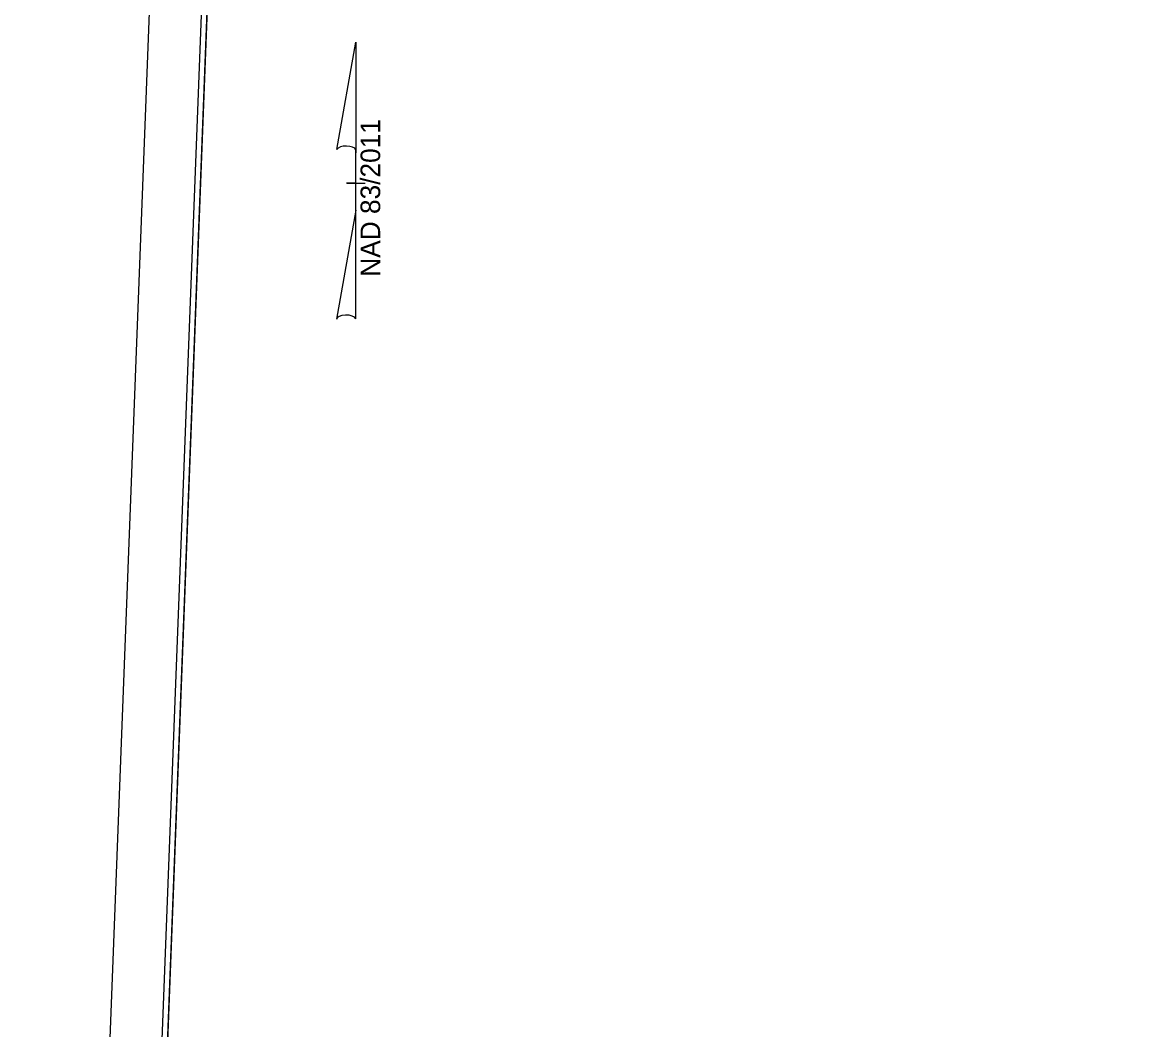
# Model space of a CAD drawing. Extents: x 2097096 to 2098260, y 686401 to 688363.
# Drawn here: x 2097096 to 2097581, y 687501.6 to 687937.5 of the extents above; entities that cross this region are included whole.
import ezdxf

# ---------------------------------------------------------------- set-up
doc = ezdxf.new("R2010")
doc.units = 0
for name, color, linetype in [('Prop North Arrow NAD83 for Plan Sheets CELL', 7, 'Continuous'), ('Sheet Layout Plan Border', 7, 'Continuous'), ('Sheet Plot Border Inside CELL', 7, 'Continuous'), ('Sheet Plot Border Outside CELL', 7, 'Continuous'), ('Sheet Profile CELL', 7, 'Continuous')]:
    doc.layers.add(name, color=color, linetype=linetype)

msp = doc.modelspace()

# ---------------------------------------------------------------- linework, layer by layer
at = {"layer": 'Prop North Arrow NAD83 for Plan Sheets CELL'}
for p, q in [((2097231.99, 687882.56), (2097240.19, 687928.91)), ((2097240.24, 687928.91), (2097240.19, 687928.91)), ((2097240.24, 687928.91), (2097240.19, 687928.91)), ((2097240.24, 687928.91), (2097240.24, 687881.11)), ((2097240.24, 687856.31), (2097240.24, 687882.51)), ((2097240.24, 687881.11), (2097240.24, 687882.46)), ((2097236.24, 687867.91), (2097236.19, 687867.91)), ((2097239.79, 687867.91), (2097236.24, 687867.91)), ((2097236.29, 687867.91), (2097244.29, 687867.91)), ((2097240.24, 687856.31), (2097231.89, 687809.06)), ((2097240.29, 687809.26), (2097240.24, 687856.31))]:
    msp.add_line(p, q, dxfattribs=at)
for centre, start_param, end_param in [((2097236.13, 687882.06), 0.216388, 2.908219), ((2097236.13, 687808.89), 0.201328, 3.141593)]:
    msp.add_ellipse(centre, major_axis=(4.23, -0.03), ratio=0.461098, start_param=start_param, end_param=end_param, dxfattribs=at)
at = {"layer": 'Sheet Layout Plan Border'}
msp.add_lwpolyline([(2098179.19, 686705.44), (2097129.59, 686735.95), (2097177.17, 687976.48), (2097364.33, 687969.3), (2097368.7, 688083.22), (2098230.76, 688050.16)], close=True, dxfattribs=at)
at = {"layer": 'Sheet Plot Border Inside CELL'}
msp.add_lwpolyline([(2098173.22, 686483.26), (2098237.09, 688148.54), (2097182.76, 688188.97), (2097118.9, 686523.7)], close=True, dxfattribs=at)
at = {"layer": 'Sheet Plot Border Outside CELL'}
msp.add_lwpolyline([(2098195.16, 686469.41), (2098259.69, 688152.17), (2097160.5, 688194.33), (2097095.97, 686511.57)], close=True, dxfattribs=at)
at = {"layer": 'Sheet Profile CELL'}
msp.add_lwpolyline([(2097184.83, 688176.38), (2097127.35, 686677.48), (2098176.58, 686637.25), (2098234.06, 688136.14)], close=True, dxfattribs=at)

# ---------------------------------------------------------------- texts
at = {"layer": 'Prop North Arrow NAD83 for Plan Sheets CELL'}
msp.add_text('NAD 83/2011', height=8.5, rotation=90, dxfattribs=at).set_placement((2097250.76, 687827.44))

doc.saveas('drawing.dxf')
